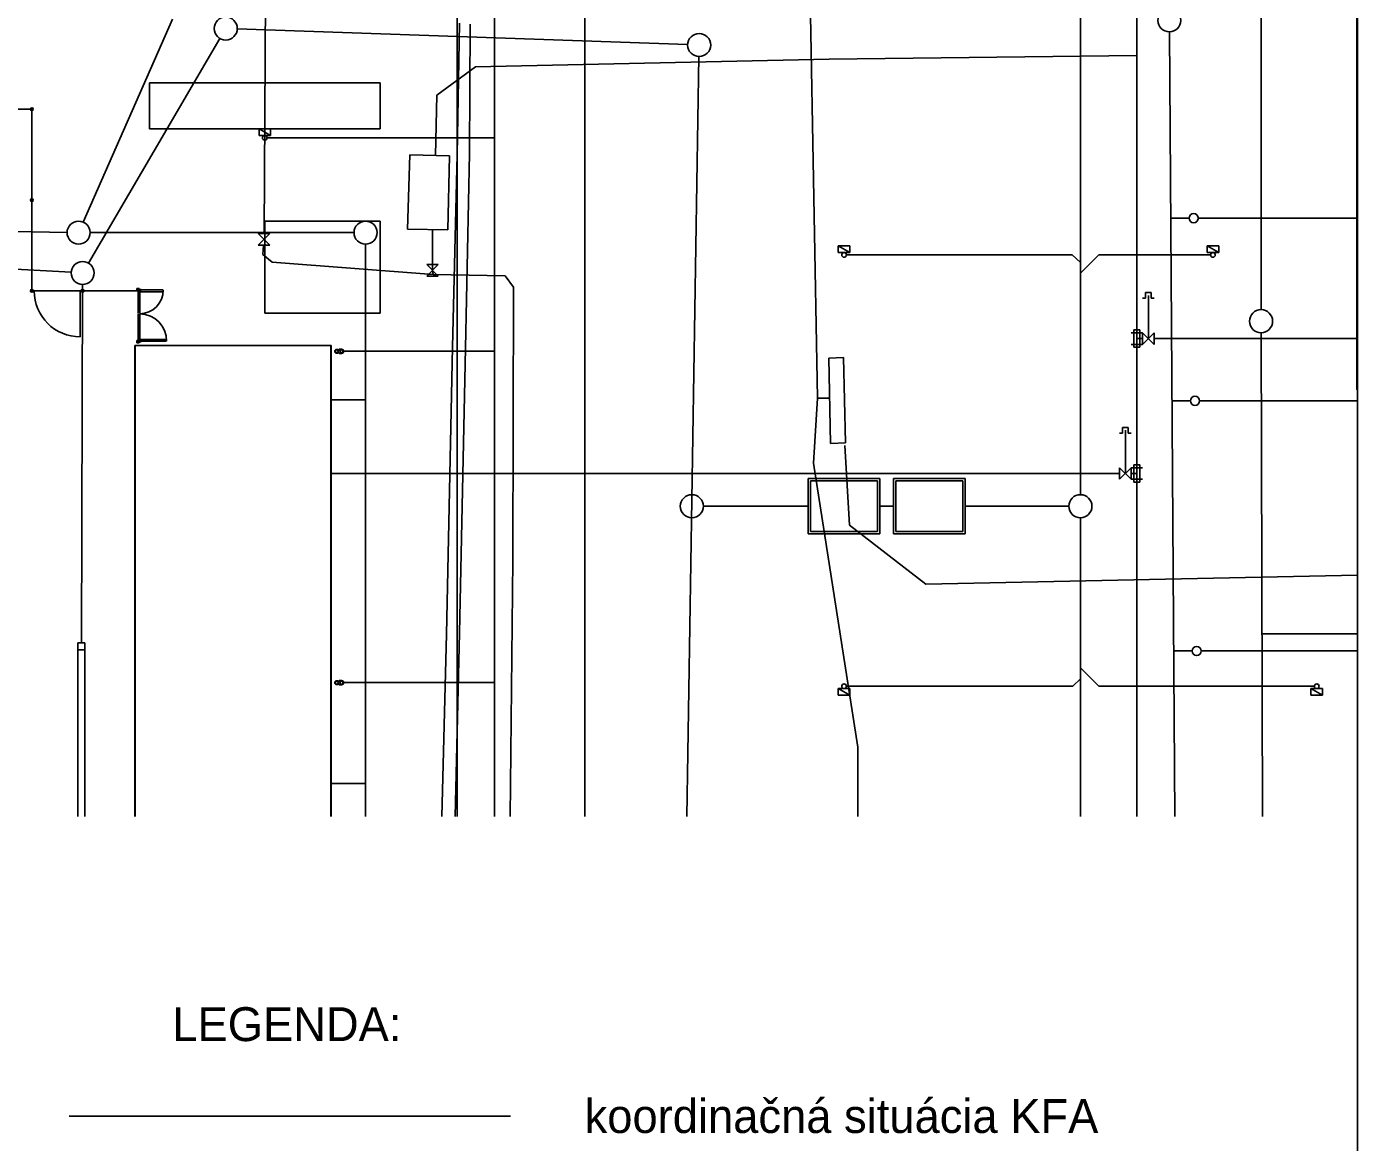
# Model space of a CAD drawing. Extents: x -264125 to -263915, y -1242307 to -1242159.
# Drawn here: x -263972.3 to -263914.6, y -1242232.4 to -1242183.9 of the extents above; entities that cross this region are included whole.
import ezdxf

# ---------------------------------------------------------------- set-up
doc = ezdxf.new("R2010")
doc.units = 0
for name, color, linetype in [('KFA_JESTV_IS_DSP', 7, 'Continuous'), ('KFA_SITUACIA_DSP', 7, 'Continuous'), ('LEGENDA', 7, 'Continuous'), ('RAM_NA_TLAC_A3_1-500', 7, 'Continuous')]:
    doc.layers.add(name, color=color, linetype=linetype)

msp = doc.modelspace()

# ---------------------------------------------------------------- linework, layer by layer
at = {"layer": 'KFA_JESTV_IS_DSP'}
for p, q in [((-263961.816, -1242158.913), (-263961.999, -1242192.922)), ((-263937.993, -1242200.068), (-263938.759, -1242158.913)), ((-263918.763, -1242158.913), (-263918.757, -1242196.225)), ((-263965.974, -1242183.616), (-263969.841, -1242192.426)), ((-263943.628, -1242184.728), (-263963.161, -1242184.046)), ((-263953.528, -1242183.799), (-263953.63, -1242189.514)), ((-263953.083, -1242189.456), (-263953.067, -1242183.845)), ((-263922.503, -1242218.208), (-263922.731, -1242184.174)), ((-263963.914, -1242184.46), (-263969.615, -1242194.201)), ((-263952.832, -1242185.692), (-263937.488, -1242185.363)), ((-263943.659, -1242218.208), (-263943.136, -1242185.245)), ((-263937.488, -1242185.363), (-263924.143, -1242185.192)), ((-263954.509, -1242186.913), (-263952.832, -1242185.692)), ((-263954.57, -1242189.535), (-263954.509, -1242186.913)), ((-263955.775, -1242192.739), (-263955.679, -1242189.503)), ((-263955.679, -1242189.503), (-263953.955, -1242189.552)), ((-263953.955, -1242189.552), (-263954.033, -1242192.766)), ((-263953.63, -1242189.514), (-263953.822, -1242197.849)), ((-263953.266, -1242197.902), (-263953.083, -1242189.456)), ((-263970.367, -1242194.605), (-264044.102, -1242190.483)), ((-263970.542, -1242192.875), (-264044.328, -1242191.641)), ((-263954.033, -1242192.766), (-263955.775, -1242192.739)), ((-263954.693, -1242194.518), (-263954.696, -1242192.756)), ((-263962.251, -1242192.922), (-263961.751, -1242192.922)), ((-263961.751, -1242192.922), (-263962.251, -1242193.422)), ((-263961.751, -1242193.422), (-263962.251, -1242192.922)), ((-263962.251, -1242193.422), (-263961.751, -1242193.422)), ((-263962.017, -1242193.422), (-263962.046, -1242193.838)), ((-263962.046, -1242193.838), (-263961.65, -1242194.164)), ((-263961.65, -1242194.164), (-263954.663, -1242194.7)), ((-263954.943, -1242194.268), (-263954.443, -1242194.268)), ((-263954.443, -1242194.268), (-263954.943, -1242194.768)), ((-263954.443, -1242194.768), (-263954.943, -1242194.268)), ((-263954.663, -1242194.7), (-263954.693, -1242194.518)), ((-263954.943, -1242194.768), (-263954.443, -1242194.768)), ((-263954.663, -1242194.7), (-263951.539, -1242194.754)), ((-263951.539, -1242194.754), (-263951.176, -1242195.243)), ((-263951.176, -1242195.243), (-263951.207, -1242207.105)), ((-263918.755, -1242197.225), (-263918.689, -1242218.208)), ((-263953.822, -1242197.849), (-263954.091, -1242210.31)), ((-263953.525, -1242210.24), (-263953.266, -1242197.902)), ((-263936.861, -1242198.305), (-263937.501, -1242198.334)), ((-263937.501, -1242198.334), (-263937.428, -1242202.028)), ((-263937.501, -1242198.334), (-263937.501, -1242198.334)), ((-263936.776, -1242202.003), (-263936.861, -1242198.305)), ((-263937.993, -1242200.068), (-263938.174, -1242202.878)), ((-263937.993, -1242200.068), (-263937.467, -1242200.068)), ((-263937.428, -1242202.028), (-263936.776, -1242202.003)), ((-263936.81, -1242202.117), (-263936.602, -1242205.569)), ((-263938.174, -1242202.878), (-263936.242, -1242215.207)), ((-263936.602, -1242205.569), (-263933.291, -1242208.127)), ((-263951.207, -1242207.105), (-263951.324, -1242218.208)), ((-263933.291, -1242208.127), (-263914.579, -1242207.739)), ((-263954.091, -1242210.31), (-263954.291, -1242218.208)), ((-263953.707, -1242218.208), (-263953.525, -1242210.24)), ((-263936.242, -1242215.207), (-263936.248, -1242218.208))]:
    msp.add_line(p, q, dxfattribs=at)
for centre in [(-263963.661, -1242184.028), (-263922.734, -1242183.674), (-263943.128, -1242184.745), (-263970.042, -1242192.883), (-263969.868, -1242194.633), (-263918.757, -1242196.725)]:
    msp.add_circle(centre, 0.5, dxfattribs=at)
at = {"layer": 'KFA_SITUACIA_DSP'}
for p, q in [((-263953.617, -1242218.208), (-263953.617, -1242158.913)), ((-263948.093, -1242158.913), (-263948.093, -1242218.208)), ((-263926.593, -1242158.913), (-263926.593, -1242204.252)), ((-263924.143, -1242158.913), (-263924.143, -1242185.14)), ((-263914.6, -1242168.728), (-263914.6, -1242199.693)), ((-263952, -1242218.208), (-263952, -1242182)), ((-263924.143, -1242185.14), (-263924.143, -1242218.208)), ((-263966.968, -1242186.382), (-263956.968, -1242186.382)), ((-263966.968, -1242188.382), (-263966.968, -1242186.382)), ((-263956.968, -1242186.382), (-263956.968, -1242188.382)), ((-263972.068, -1242187.532), (-264118.068, -1242187.532)), ((-263972.128, -1242187.532), (-263972.008, -1242187.532)), ((-263972.068, -1242187.592), (-263972.068, -1242187.472)), ((-263972.068, -1242195.407), (-263972.068, -1242187.532)), ((-263956.968, -1242188.382), (-263966.968, -1242188.382)), ((-263962.218, -1242188.382), (-263961.718, -1242188.382)), ((-263962.218, -1242188.672), (-263962.218, -1242188.382)), ((-263962.218, -1242188.382), (-263961.718, -1242188.672)), ((-263962.218, -1242188.382), (-263961.718, -1242188.672)), ((-263961.718, -1242188.382), (-263962.218, -1242188.382)), ((-263961.718, -1242188.672), (-263962.218, -1242188.672)), ((-263961.868, -1242188.772), (-263952, -1242188.772)), ((-263961.718, -1242188.382), (-263961.718, -1242188.672)), ((-263961.718, -1242188.672), (-263961.718, -1242188.382)), ((-263972.128, -1242191.47), (-263972.008, -1242191.47)), ((-263972.068, -1242191.41), (-263972.068, -1242191.53)), ((-263921.877, -1242192.257), (-263922.677, -1242192.257)), ((-263915.293, -1242192.257), (-263921.477, -1242192.257)), ((-263914.579, -1242192.257), (-263915.293, -1242192.257)), ((-263961.968, -1242192.382), (-263956.968, -1242192.382)), ((-263961.968, -1242196.382), (-263961.968, -1242192.382)), ((-263956.968, -1242192.382), (-263956.968, -1242196.382)), ((-263958.097, -1242192.883), (-263969.542, -1242192.883)), ((-263957.597, -1242218.208), (-263957.597, -1242193.383)), ((-263937.093, -1242193.752), (-263937.093, -1242193.462)), ((-263937.093, -1242193.462), (-263936.593, -1242193.462)), ((-263936.593, -1242193.752), (-263937.093, -1242193.462)), ((-263936.593, -1242193.752), (-263937.093, -1242193.462)), ((-263937.093, -1242193.462), (-263937.093, -1242193.752)), ((-263936.593, -1242193.752), (-263937.093, -1242193.752)), ((-263937.093, -1242193.752), (-263936.593, -1242193.752)), ((-263936.743, -1242193.852), (-263926.953, -1242193.852)), ((-263936.593, -1242193.462), (-263936.593, -1242193.752)), ((-263926.953, -1242193.852), (-263926.593, -1242194.178)), ((-263925.798, -1242193.852), (-263926.593, -1242194.648)), ((-263920.944, -1242193.852), (-263925.798, -1242193.852)), ((-263921.093, -1242193.752), (-263921.093, -1242193.462)), ((-263921.093, -1242193.462), (-263920.593, -1242193.462)), ((-263920.593, -1242193.752), (-263921.093, -1242193.462)), ((-263920.593, -1242193.752), (-263921.093, -1242193.462)), ((-263921.093, -1242193.462), (-263921.093, -1242193.752)), ((-263920.593, -1242193.752), (-263921.093, -1242193.752)), ((-263921.093, -1242193.752), (-263920.593, -1242193.752)), ((-263920.593, -1242193.462), (-263920.593, -1242193.752)), ((-263969.921, -1242210.683), (-263969.869, -1242195.133)), ((-263972.068, -1242195.407), (-263967.418, -1242195.407)), ((-263969.968, -1242195.407), (-263969.968, -1242197.407)), ((-263967.413, -1242195.307), (-263967.513, -1242195.307)), ((-263967.513, -1242195.307), (-263967.513, -1242195.407)), ((-263967.513, -1242195.407), (-263967.413, -1242195.407)), ((-263967.425, -1242195.32), (-263967.5, -1242195.32)), ((-263967.5, -1242195.32), (-263967.5, -1242195.395)), ((-263967.5, -1242195.395), (-263967.425, -1242195.395)), ((-263967.463, -1242195.407), (-263967.463, -1242196.395)), ((-263967.388, -1242195.407), (-263967.463, -1242195.407)), ((-263967.425, -1242195.395), (-263967.425, -1242195.32)), ((-263967.425, -1242195.395), (-263967.425, -1242195.345)), ((-263967.425, -1242195.345), (-263967.325, -1242195.345)), ((-263967.413, -1242195.407), (-263967.413, -1242195.307)), ((-263967.413, -1242195.357), (-263967.363, -1242195.357)), ((-263967.388, -1242196.395), (-263967.388, -1242195.407)), ((-263967.363, -1242195.457), (-263967.388, -1242195.457)), ((-263966.388, -1242195.371), (-263967.375, -1242195.37)), ((-263967.375, -1242195.37), (-263967.375, -1242195.445)), ((-263967.375, -1242195.445), (-263966.388, -1242195.446)), ((-263967.363, -1242195.357), (-263967.363, -1242195.457)), ((-263967.325, -1242195.345), (-263967.325, -1242195.37)), ((-263923.768, -1242195.732), (-263923.893, -1242195.732)), ((-263923.768, -1242195.732), (-263923.768, -1242195.482)), ((-263923.768, -1242195.482), (-263923.518, -1242195.482)), ((-263923.643, -1242197.482), (-263923.643, -1242195.607)), ((-263923.518, -1242195.482), (-263923.518, -1242195.732)), ((-263923.518, -1242195.732), (-263923.393, -1242195.732)), ((-263967.463, -1242197.557), (-263967.463, -1242196.42)), ((-263967.388, -1242196.42), (-263967.388, -1242197.557)), ((-263956.968, -1242196.382), (-263961.968, -1242196.382)), ((-263923.893, -1242197.232), (-263924.393, -1242197.232)), ((-263924.018, -1242197.107), (-263924.268, -1242197.107)), ((-263924.268, -1242197.107), (-263924.268, -1242197.857)), ((-263924.143, -1242197.482), (-263923.893, -1242197.482)), ((-263923.893, -1242197.482), (-263924.143, -1242197.482)), ((-263924.018, -1242197.857), (-263924.018, -1242197.107)), ((-263923.893, -1242197.732), (-263923.893, -1242197.232)), ((-263923.893, -1242197.232), (-263923.393, -1242197.732)), ((-263923.393, -1242197.232), (-263923.893, -1242197.732)), ((-263923.393, -1242197.732), (-263923.393, -1242197.232)), ((-263923.393, -1242197.482), (-263915.293, -1242197.482)), ((-263914.579, -1242197.482), (-263915.293, -1242197.482)), ((-263967.597, -1242197.782), (-263959.097, -1242197.782)), ((-263967.597, -1242218.208), (-263967.597, -1242197.782)), ((-263967.593, -1242218.208), (-263967.593, -1242197.782)), ((-263967.593, -1242197.782), (-263959.093, -1242197.782)), ((-263967.593, -1242197.782), (-263959.097, -1242197.782)), ((-263967.593, -1242218.208), (-263967.593, -1242197.782)), ((-263967.513, -1242197.557), (-263967.413, -1242197.557)), ((-263967.513, -1242197.657), (-263967.513, -1242197.557)), ((-263967.413, -1242197.657), (-263967.513, -1242197.657)), ((-263967.5, -1242197.57), (-263967.425, -1242197.57)), ((-263967.5, -1242197.645), (-263967.5, -1242197.57)), ((-263967.425, -1242197.645), (-263967.5, -1242197.645)), ((-263967.478, -1242197.782), (-263967.358, -1242197.782)), ((-263967.388, -1242197.557), (-263967.463, -1242197.557)), ((-263967.425, -1242197.57), (-263967.425, -1242197.62)), ((-263967.425, -1242197.57), (-263967.425, -1242197.645)), ((-263967.425, -1242197.62), (-263967.325, -1242197.62)), ((-263967.413, -1242197.557), (-263967.413, -1242197.657)), ((-263967.413, -1242197.607), (-263967.363, -1242197.607)), ((-263967.363, -1242197.507), (-263967.388, -1242197.507)), ((-263967.375, -1242197.52), (-263966.238, -1242197.52)), ((-263967.375, -1242197.595), (-263967.375, -1242197.52)), ((-263966.238, -1242197.595), (-263967.375, -1242197.595)), ((-263967.363, -1242197.607), (-263967.363, -1242197.507)), ((-263967.325, -1242197.62), (-263967.325, -1242197.595)), ((-263959.097, -1242197.782), (-263959.096, -1242218.208)), ((-263959.097, -1242197.782), (-263959.097, -1242218.208)), ((-263959.093, -1242197.782), (-263959.093, -1242218.208)), ((-263958.799, -1242197.962), (-263958.762, -1242197.962)), ((-263958.762, -1242197.962), (-263958.742, -1242197.942)), ((-263958.742, -1242197.942), (-263958.637, -1242197.942)), ((-263958.575, -1242198.032), (-263952, -1242198.032)), ((-263923.893, -1242197.732), (-263924.393, -1242197.732)), ((-263924.268, -1242197.857), (-263924.018, -1242197.857)), ((-263958.799, -1242198.102), (-263958.762, -1242198.102)), ((-263958.762, -1242198.102), (-263958.742, -1242198.122)), ((-263958.742, -1242198.122), (-263958.637, -1242198.122)), ((-263914.6, -1242199.693), (-263914.579, -1242199.714)), ((-263959.097, -1242200.132), (-263957.597, -1242200.132)), ((-263921.824, -1242200.182), (-263922.624, -1242200.182)), ((-263915.293, -1242200.182), (-263921.424, -1242200.182)), ((-263914.579, -1242200.182), (-263915.293, -1242200.182)), ((-263924.768, -1242201.332), (-263924.768, -1242201.582)), ((-263924.518, -1242201.332), (-263924.768, -1242201.332)), ((-263924.643, -1242203.332), (-263924.643, -1242201.457)), ((-263924.518, -1242201.582), (-263924.518, -1242201.332)), ((-263924.768, -1242201.582), (-263924.893, -1242201.582)), ((-263924.518, -1242201.582), (-263924.393, -1242201.582)), ((-263924.893, -1242203.582), (-263924.893, -1242203.082)), ((-263924.393, -1242203.082), (-263924.893, -1242203.582)), ((-263924.893, -1242203.082), (-263924.393, -1242203.582)), ((-263924.393, -1242203.582), (-263924.393, -1242203.082)), ((-263924.393, -1242203.082), (-263923.893, -1242203.082)), ((-263924.268, -1242203.707), (-263924.268, -1242202.957)), ((-263924.268, -1242202.957), (-263924.018, -1242202.957)), ((-263924.018, -1242202.957), (-263924.018, -1242203.707)), ((-263959.097, -1242203.332), (-263958.097, -1242203.332)), ((-263924.893, -1242203.332), (-263958.097, -1242203.332)), ((-263938.393, -1242203.552), (-263935.293, -1242203.552)), ((-263938.393, -1242205.952), (-263938.393, -1242203.552)), ((-263938.293, -1242205.852), (-263938.293, -1242203.652)), ((-263938.293, -1242203.652), (-263935.393, -1242203.652)), ((-263935.393, -1242205.852), (-263935.393, -1242203.652)), ((-263935.293, -1242205.952), (-263935.293, -1242203.552)), ((-263934.693, -1242203.552), (-263931.593, -1242203.552)), ((-263934.693, -1242203.552), (-263934.693, -1242205.952)), ((-263934.593, -1242203.652), (-263934.593, -1242205.852)), ((-263934.593, -1242203.652), (-263931.693, -1242203.652)), ((-263931.693, -1242203.652), (-263931.693, -1242205.852)), ((-263931.593, -1242203.552), (-263931.593, -1242205.952)), ((-263924.143, -1242203.332), (-263924.393, -1242203.332)), ((-263924.393, -1242203.332), (-263924.143, -1242203.332)), ((-263924.393, -1242203.582), (-263923.893, -1242203.582)), ((-263924.018, -1242203.707), (-263924.268, -1242203.707)), ((-263938.393, -1242204.752), (-263942.945, -1242204.752)), ((-263934.693, -1242204.752), (-263935.293, -1242204.752)), ((-263927.093, -1242204.752), (-263931.593, -1242204.752)), ((-263926.593, -1242218.208), (-263926.593, -1242205.252)), ((-263935.293, -1242205.952), (-263938.393, -1242205.952)), ((-263935.393, -1242205.852), (-263938.293, -1242205.852)), ((-263931.593, -1242205.952), (-263934.693, -1242205.952)), ((-263931.693, -1242205.852), (-263934.593, -1242205.852)), ((-263970.071, -1242210.684), (-263969.77, -1242210.682)), ((-263970.071, -1242218.208), (-263970.071, -1242210.684)), ((-263969.77, -1242210.682), (-263969.77, -1242218.208)), ((-263914.579, -1242210.282), (-263918.714, -1242210.282)), ((-263970.071, -1242210.983), (-263969.771, -1242210.985)), ((-263921.751, -1242211.032), (-263922.551, -1242211.032)), ((-263914.579, -1242211.032), (-263921.351, -1242211.032)), ((-263925.798, -1242212.562), (-263926.593, -1242211.767)), ((-263958.799, -1242212.337), (-263958.762, -1242212.337)), ((-263958.799, -1242212.477), (-263958.762, -1242212.477)), ((-263958.762, -1242212.337), (-263958.742, -1242212.317)), ((-263958.762, -1242212.477), (-263958.742, -1242212.497)), ((-263958.742, -1242212.317), (-263958.637, -1242212.317)), ((-263958.742, -1242212.497), (-263958.637, -1242212.497)), ((-263958.575, -1242212.407), (-263952, -1242212.407)), ((-263926.919, -1242212.562), (-263926.593, -1242212.237)), ((-263937.093, -1242212.952), (-263937.093, -1242212.662)), ((-263937.093, -1242212.662), (-263936.593, -1242212.662)), ((-263936.593, -1242212.952), (-263937.093, -1242212.662)), ((-263936.593, -1242212.952), (-263937.093, -1242212.662)), ((-263937.093, -1242212.662), (-263937.093, -1242212.952)), ((-263936.593, -1242212.952), (-263937.093, -1242212.952)), ((-263937.093, -1242212.952), (-263936.593, -1242212.952)), ((-263936.743, -1242212.562), (-263926.919, -1242212.562)), ((-263936.593, -1242212.662), (-263936.593, -1242212.952)), ((-263916.443, -1242212.562), (-263925.798, -1242212.562)), ((-263916.593, -1242212.952), (-263916.593, -1242212.662)), ((-263916.593, -1242212.662), (-263916.093, -1242212.662)), ((-263916.093, -1242212.952), (-263916.593, -1242212.662)), ((-263916.093, -1242212.952), (-263916.593, -1242212.662)), ((-263916.593, -1242212.662), (-263916.593, -1242212.952)), ((-263916.093, -1242212.952), (-263916.593, -1242212.952)), ((-263916.593, -1242212.952), (-263916.093, -1242212.952)), ((-263916.093, -1242212.662), (-263916.093, -1242212.952)), ((-263959.097, -1242216.782), (-263957.597, -1242216.782))]:
    msp.add_line(p, q, dxfattribs=at)
for centre, radius in [((-263972.068, -1242187.532), 0.06), ((-263961.968, -1242188.772), 0.1), ((-263972.068, -1242191.47), 0.06), ((-263921.677, -1242192.257), 0.2), ((-263957.597, -1242192.883), 0.5), ((-263936.843, -1242193.852), 0.1), ((-263920.844, -1242193.852), 0.1), ((-263969.868, -1242194.633), 0.5), ((-263972.068, -1242195.407), 0.06), ((-263969.868, -1242195.407), 0.06), ((-263958.847, -1242198.032), 0.085), ((-263958.847, -1242198.032), 0.0625), ((-263958.637, -1242198.032), 0.0625), ((-263921.624, -1242200.182), 0.2), ((-263943.445, -1242204.752), 0.5), ((-263926.593, -1242204.752), 0.5), ((-263921.551, -1242211.032), 0.2), ((-263958.847, -1242212.407), 0.085), ((-263958.847, -1242212.407), 0.0625), ((-263958.637, -1242212.407), 0.0625), ((-263936.843, -1242212.562), 0.1), ((-263916.343, -1242212.562), 0.1)]:
    msp.add_circle(centre, radius, dxfattribs=at)
for centre, radius, start, end in [((-263969.968, -1242195.407), 2, 180, 270), ((-263967.4, -1242195.382), 1.025, 270.60954, 0.60953), ((-263967.4, -1242197.582), 1.175, 359.39047, 89.39046), ((-263958.637, -1242198.032), 0.09, 270, 90), ((-263958.637, -1242212.407), 0.09, 270, 90)]:
    msp.add_arc(centre, radius, start, end, dxfattribs=at)
for centre in [(-263967.4, -1242195.382), (-263967.4, -1242195.382), (-263967.4, -1242197.582)]:
    msp.add_ellipse(centre, major_axis=(0, 0.0125), ratio=0.999995, dxfattribs=at)
at = {"layer": 'LEGENDA'}
msp.add_line((-263970.446, -1242231.208), (-263951.307, -1242231.208), dxfattribs=at)
at = {"layer": 'RAM_NA_TLAC_A3_1-500'}
msp.add_lwpolyline([(-264124.579, -1242158.913), (-263914.579, -1242158.913), (-263914.579, -1242307.413), (-264124.579, -1242307.413)], close=True, dxfattribs=at)

# ---------------------------------------------------------------- texts
at = {"layer": 'LEGENDA'}
for s, height, p in [('LEGENDA:', 1.4695, (-263965.979, -1242227.957)), ('koordinačná situácia KFA', 1.46953, (-263948.096, -1242231.943))]:
    msp.add_text(s, height=height, dxfattribs=at).set_placement(p)

doc.saveas('drawing.dxf')
